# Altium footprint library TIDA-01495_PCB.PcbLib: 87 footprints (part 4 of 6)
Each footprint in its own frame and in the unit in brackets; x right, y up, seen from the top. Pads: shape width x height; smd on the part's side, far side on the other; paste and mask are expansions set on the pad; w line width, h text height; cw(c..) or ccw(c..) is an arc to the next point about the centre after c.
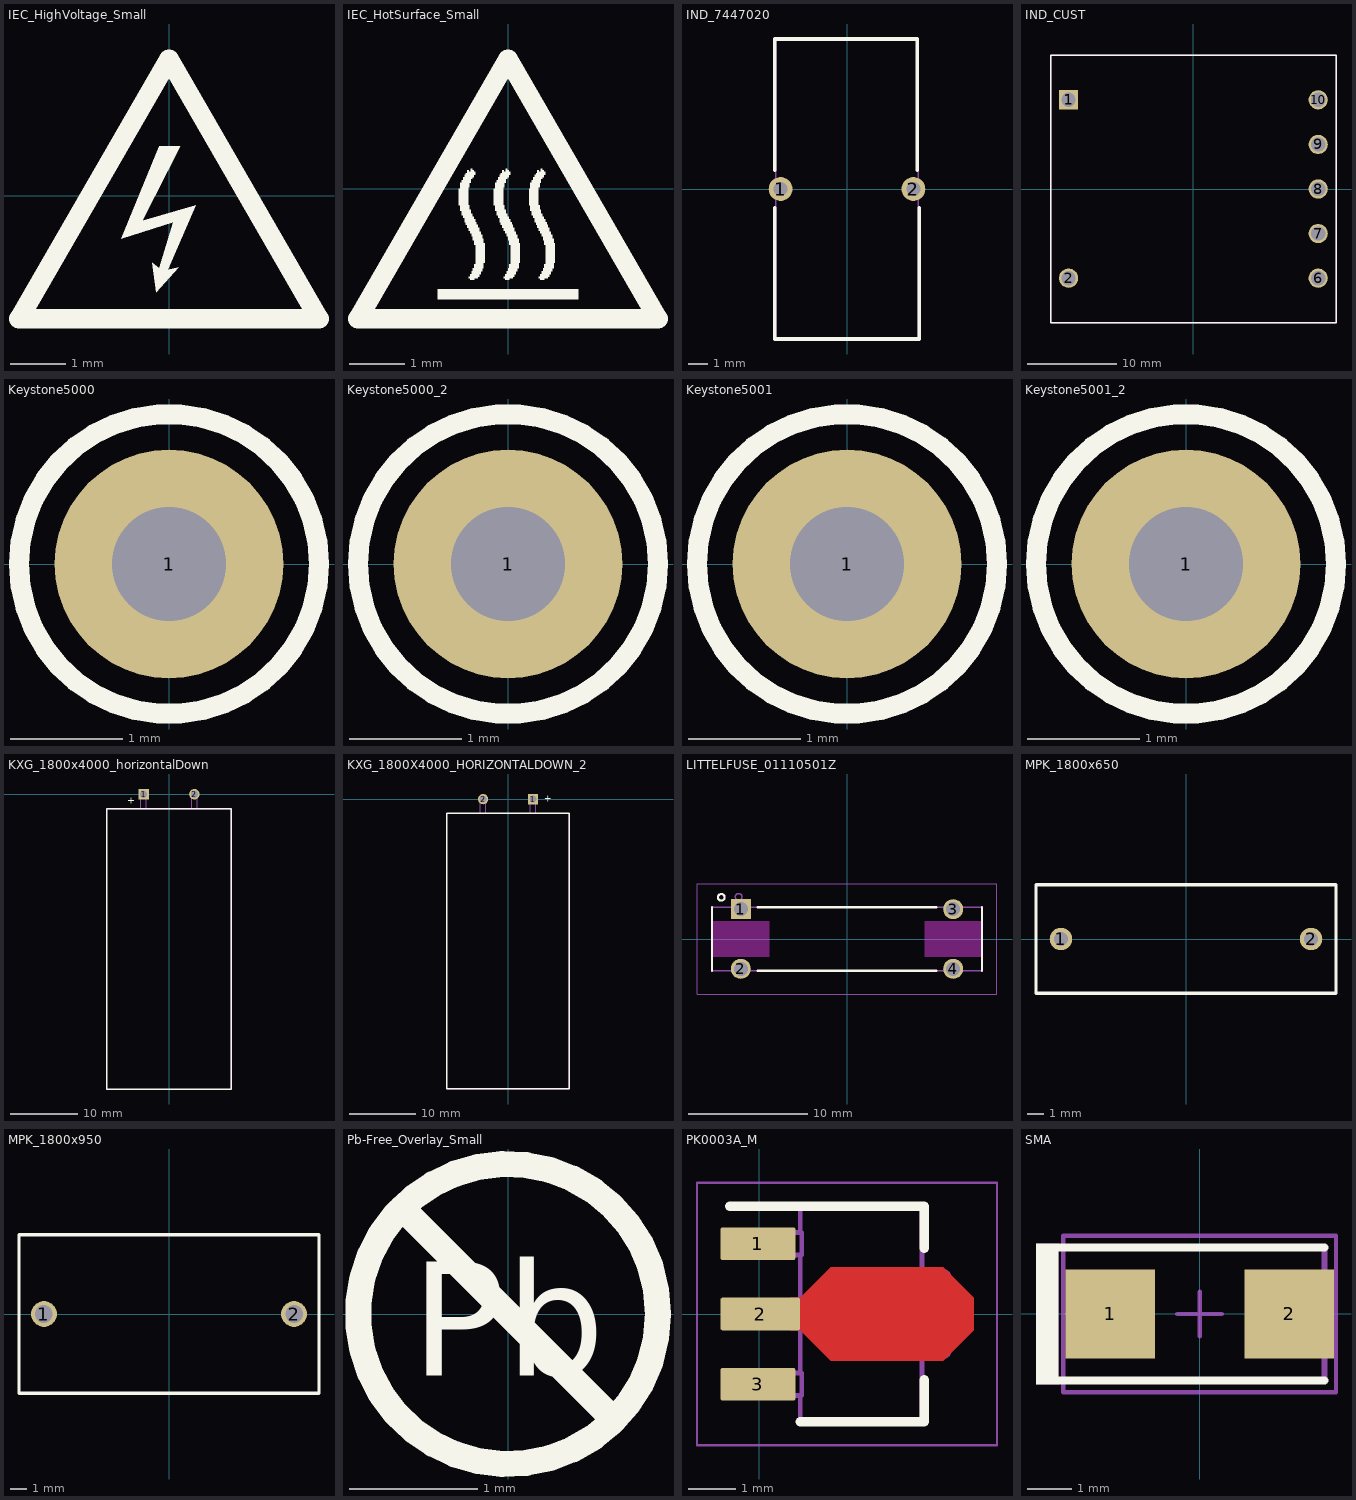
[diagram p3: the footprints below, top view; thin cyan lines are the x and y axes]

## IEC_HighVoltage_Small [mm]
Top Overlay:
  region: -0.178,0.889 0.203,0.889 -0.483,-0.457 0.483,-0.178 -0.025,-1.346 0.178,-1.295 -0.229,-1.753 -0.305,-1.219 -0.178,-1.321 0.076,-0.483 -0.864,-0.787
  lines w0.356: -2.718,-2.235 2.718,-2.235 0,2.472 -2.718,-2.235

## IEC_HotSurface_Small [mm]
Top Overlay:
  drawing of 10 lines, arcs and shapes, not listed

## IND_7447020 [mm] "WURTH ELEKTRONIK"
height 15.8
pads (2):
  round 1.25 hole 0.75: 1(-3.5,0) 2(3.5,0)
Top Overlay:
  lines w0.2: -3.8,-1 -3.8,-7.9 3.8,-7.9 3.8,-1 ; -3.8,1 -3.8,7.9 3.7,7.9 3.7,1
Mechanical 5:
  lines w0.1: -3.75,-7.9 3.75,-7.9 3.75,7.9 -3.75,7.9 -3.75,-7.9
  text ".Designator" at -0.999,-0.888 h1.02
3D body: height 15.78, standoff 0.02, extent -3.8,-7.838 3.7,7.9
3D body: height 2, standoff -4, extent 3.252,-0.249 3.75,0.25
3D body: height 2, standoff -4, extent -3.748,-0.249 -3.25,0.25

## IND_CUST [mm]
pads (7):
  rect 2.159x2.159 hole 1.6: 1(-14,10)
  round 2.159 hole 1.6: 2(-14,-10) 6(14,-10) 7(14,-5) 8(14,0) 9(14,5) 10(14,10)
Top Overlay:
  lines w0.152: -16,-15 -16,15 16,15 16,-15 -16,-15
Mechanical 5:
  lines w0.152: -16,-15 16,-15 16,15 -16,15 -16,-15
  text ".Designator" at -0.911,-0.809 h0.76
3D body: height 13, standoff 0, extent -16.002,-15 16.002,14.972

## Keystone5000 [mil] "For Keystone 500x miniature loop terminals"
height 181.1
pads (1):
  round 80 hole 40: 1(0,0)
Top Overlay:
  circle w7: c0,0 r52.5
Mechanical 5:
  circle w3.94: c0,0 r52.5
  text ".Designator" at -6.86,28.6 h18
3D body "Keystone_5000.stp": height 181.97, standoff -118.11, extent -49,-49 49.04,49.24

## Keystone5000_2 [mil]
pads (1):
  round 80 hole 40: 1(0,0)
Top Overlay:
  circle w7: c0,0 r52.5
Mechanical 5:
  circle w3.94: c0,0 r52.5
  text ".Designator" at -20.25,29.4 h18
3D body "Keystone_5000.stp": height 181.97, standoff -118.11, extent -49,-49 49.04,49.24

## Keystone5001 [mil] "For Keystone 500x miniature loop terminals"
height 181.1
pads (1):
  round 80 hole 40: 1(0,0)
Top Overlay:
  circle w7: c0,0 r52.5
Mechanical 5:
  circle w3.94: c0,0 r52.5
  text ".Designator" at -92.97,-15 h18
3D body "Keystone_5001.stp": height 181.97, standoff -118.11, extent -49,-49 49.04,49.24

## Keystone5001_2 [mil]
pads (1):
  round 80 hole 40: 1(0,0)
Top Overlay:
  circle w7: c0,0 r52.5
Mechanical 5:
  circle w3.94: c0,0 r52.5
  text ".Designator" at -12.85,26.71 h18
3D body "Keystone_5001.stp": height 181.97, standoff -118.11, extent -49,-49 49.04,49.24

## KXG_1800x4000_horizontalDown [mm] "TH, 2-Leads, Dia 18mm, Pin Spacing 7.5mm"
height 18.5
pads (2):
  rect 1.55x1.55 hole 1.05: 1(-3.75,0)
  round 1.55 hole 1.05: 2(3.75,0)
Top Overlay:
  lines w0.2: -9.25,-43.65 8.962,-43.65 9.25,-43.65 9.25,-2.15 8.962,-2.15 -9.25,-2.15 -9.25,-43.65
  text "+" at -6.198,-0.515 h1.02
Mechanical 5:
  lines w0.1: -4.15,-2.15 -4.15,-1.2 -4.15,0 cw(c-3.75,0) -3.35,0 -3.35,-1.2 -3.35,-2.15 ; 3.35,-2.15 3.35,-1.2 3.35,0 cw(c3.75,0) 4.15,0 4.15,-1.2 4.15,-2.15 ; -9.25,-43.65 -9.25,-2.15 8.962,-2.15 9.25,-2.15 9.25,-43.65 8.962,-43.65 -9.25,-43.65
  text ".Designator" at 1.463,-24.873 h1.02
  text "+" at -6.218,-0.515 h1.02
3D body "KXG_1800x4000_DOWN.stp": height 18.5, standoff -4, extent -9.26,-43.65 9.25,0.399

## KXG_1800X4000_HORIZONTALDOWN_2 [mm]
pads (2):
  rect 1.55x1.55 hole 1.05: 1(3.75,0)
  round 1.55 hole 1.05: 2(-3.75,0)
Top Overlay:
  lines w0.2: -9.25,-43.65 -9.25,-2.15 8.962,-2.15 9.25,-2.15 9.25,-43.65 8.962,-43.65 -9.25,-43.65
  text "+" at 5.461,0.508 h1.02
Mechanical 5:
  lines w0.1: -4.15,-2.15 -4.15,-1.2 -4.15,0 cw(c-3.75,0) -3.35,0 -3.35,-1.2 -3.35,-2.15 ; 3.35,-2.15 3.35,-1.2 3.35,0 cw(c3.75,0) 4.15,0 4.15,-1.2 4.15,-2.15 ; -9.25,-43.65 8.962,-43.65 9.25,-43.65 9.25,-2.15 8.962,-2.15 -9.25,-2.15 -9.25,-43.65
  text "+" at 5.461,0.508 h1.02
  text ".Designator" at 0.74,-23.171 h1.02
3D body "KXG_1800x4000_DOWN.stp": height 18.5, standoff -4, extent -9.26,-43.65 9.25,0.399

## LITTELFUSE_01110501Z [mm] "FUSE CLIP, CARTRIDGE, 250V, 10A, PCB"
height 7.1
pads (4):
  rect 1.67x1.67 / inner round 1.67 / far side rect 1.67x1.67 hole 1.17: 1(-8.9,2.5)
  round 1.67 hole 1.17: 2(-8.9,-2.5) 3(8.9,2.5) 4(8.9,-2.5)
Top Layer keep-out:
  rectangle: 6.5,-1.501 11.3,1.499
  rectangle: -11.3,-1.501 -6.5,1.499
Top Overlay:
  circle w0.178: c-10.533,3.493 r0.279
  lines w0.178: -11.3,-2.66 -11.3,2.66 ; -7.5,-2.66 7.5,-2.66 ; -7.5,2.66 7.5,2.66 ; 11.3,-2.66 11.3,2.66
Bottom Overlay:
  lines w0.178: -11.3,-2.66 -11.3,-0.985 ; -11.3,0.985 -11.3,2.66 ; -7.5,-2.66 -5.825,-2.66 ; -7.5,2.66 -5.825,2.66 ; -4.15,-2.66 -2.475,-2.66 ; -4.15,2.66 -2.475,2.66 ; -0.8,-2.66 0.875,-2.66 ; -0.8,2.66 0.875,2.66 ; 2.55,-2.66 4.225,-2.66 ; 2.55,2.66 4.225,2.66 ; 5.825,2.66 7.5,2.66 ; 5.9,-2.66 7.575,-2.66 ; 11.3,-2.66 11.3,-0.985 ; 11.3,0.985 11.3,2.66
Mechanical 5:
  circle w0.127: c-9.076,3.53 r0.279
  lines w0.127: -11.3,-2.66 11.3,-2.66 11.3,2.66 -11.3,2.66 -11.3,-2.66
  text ".Designator" at -0.447,-0.816 h0.76
Mechanical 15:
  lines w0.05: -12.57,-4.63 -12.57,4.63 12.57,4.63 12.57,-4.63 -12.57,-4.63
3D body: height 7.1, standoff 0, extent -11.3,-2.66 11.3,2.66

## MPK_1800x650 [mm] "TH, 2-Leads, Body 18x6.5mm, Lead Spacing 15mm"
height 12
pads (2):
  round 1.35 hole 0.85: 1(-7.5,0) 2(7.5,0)
Top Overlay:
  lines w0.2: -9,-3.25 9,-3.25 9,3.25 -9,3.25 -9,-3.25
Mechanical 5:
  lines w0.1: -9,-3.25 -9,3.25 9,3.25 9,-3.25 -9,-3.25
  text ".Designator" at -1.524,-0.508 h1.02
3D body: height 12, standoff 1, extent -9,-3.25 9,3.25
3D body: height 0, standoff -2.5, extent -7.797,-0.299 -7.2,0.3
3D body: height 0, standoff -2.5, extent 7.202,-0.299 7.8,0.3
3D body: height 1.9, standoff -0.1, extent -8.49,-0.996 -6.5,0.996
3D body: height 1.9, standoff -0.1, extent 6.5,-0.996 8.49,0.996

## MPK_1800x950 [mm] "TH, 2-Leads, Body 18x9.5mm, Lead Spacing 15mm"
height 15
pads (2):
  round 1.55 hole 1.05: 1(-7.5,0) 2(7.5,0)
Top Overlay:
  lines w0.2: -9,-4.75 -9,4.75 9,4.75 9,-4.75 -9,-4.75
Mechanical 5:
  lines w0.1: -9,-4.75 9,-4.75 9,4.75 -9,4.75 -9,-4.75
  text ".Designator" at -0.345,-0.824 h1.02
3D body: height 14, standoff 1, extent -9,-4.75 9,4.75
3D body: height 0, standoff -2.5, extent -7.897,-0.399 -7.1,0.399
3D body: height 0, standoff -2.5, extent 7.103,-0.399 7.9,0.399
3D body: height 1.9, standoff -0.1, extent -8.5,-0.996 -6.51,0.996
3D body: height 1.9, standoff -0.1, extent 6.5,-0.996 8.49,0.996

## Pb-Free_Overlay_Small [mm]
Top Overlay:
  circle w0.203: c0,0 r1.168
  lines w0.203: -0.826,0.826 0.826,-0.826
  text "Pb" at -0.752,-0.48 h0.89

## PK0003A_M [mm] "SOT89, 3-Leads, Body 4.5x2.5mm, Pitch 1.5mm, IPC Low Density"
height 1.6
pads (3):
  rrect14% 1.6x0.7 smd: 1(-0.025,1.5) 3(-0.025,-1.5)
  rrect14% 1.7x0.7 smd: 2(0.025,0)
Top Layer:
  region: 0.875,0.35 1.525,1 3.925,1 4.575,0.35 4.575,-0.35 3.925,-1 1.525,-1 0.875,-0.35 0.675,-0.35 0.675,0.35
Top Overlay:
  lines w0.2: -0.625,2.3 3.526,2.3 3.526,1.4 ; 0.875,-2.3 3.526,-2.3 3.526,-1.4
Mechanical 5:
  lines w0.1: 0.875,-1.74 0.875,-2.3 3.475,-2.3 3.475,-0.9 ; 0.875,-1.26 0.875,-0.24 ; 0.875,0.24 0.875,1.26 ; 0.875,1.74 0.875,2.3 3.475,2.3 3.475,0.9 ; -0.325,-1.74 -0.325,-1.26 0.913,-1.26 0.913,-1.74 -0.325,-1.74 ; -0.325,-0.24 0.913,-0.24 0.913,0.24 -0.325,0.24 -0.325,-0.24 ; -0.325,1.26 0.913,1.26 0.913,1.74 -0.325,1.74 -0.325,1.26 ; 3.437,-0.9 3.437,0.9 3.947,0.9 cw(c3.947,0.8) 4.047,0.8 4.047,-0.8 cw(c3.947,-0.8) 3.947,-0.9 3.437,-0.9
  text ".Designator" at 1.475,1.85 h1.02
Mechanical 15:
  lines w0.05: -1.325,-2.8 -1.325,2.8 5.075,2.8 5.075,-2.8 -1.325,-2.8
  lines w0.1: 1.375,0 2.375,0 ; 1.875,-0.5 1.875,0.5
3D body "PK0003A.stp": height 1.6, standoff 0, extent -0.259,-2.25 3.837,2.25

## SMA [mm] "Molded Diode, 2-Leads, Body 4.3x2.6mm, IPC Medium Density, based on OnSemi component dimensions and land pattern"
height 2.27
pads (2):
  rect 2x2 smd: 1(-2,0) 2(2,0)
Top Overlay:
  rectangle: -3.658,-1.575 -3.15,1.575
  lines w0.178: -3.327,-1.486 2.794,-1.486 ; -3.327,1.486 2.794,1.486
Mechanical 5:
  rectangle: -3.658,-1.575 -3.15,1.575
  lines w0.127: -3.327,-1.486 2.794,-1.486 2.794,1.486 -3.327,1.486
  text ".Designator" at 0.758,0.565 h1.02
Mechanical 15:
  lines w0.1: -0.5,0 0.5,0 ; 0,-0.5 0,0.5 ; -3.05,-1.75 -3.05,1.75 3.05,1.75 3.05,-1.75 -3.05,-1.75
3D body "SMA_nominal.stp": height 2.42, standoff 0.02, extent -2.6,-1.3 2.6,1.3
